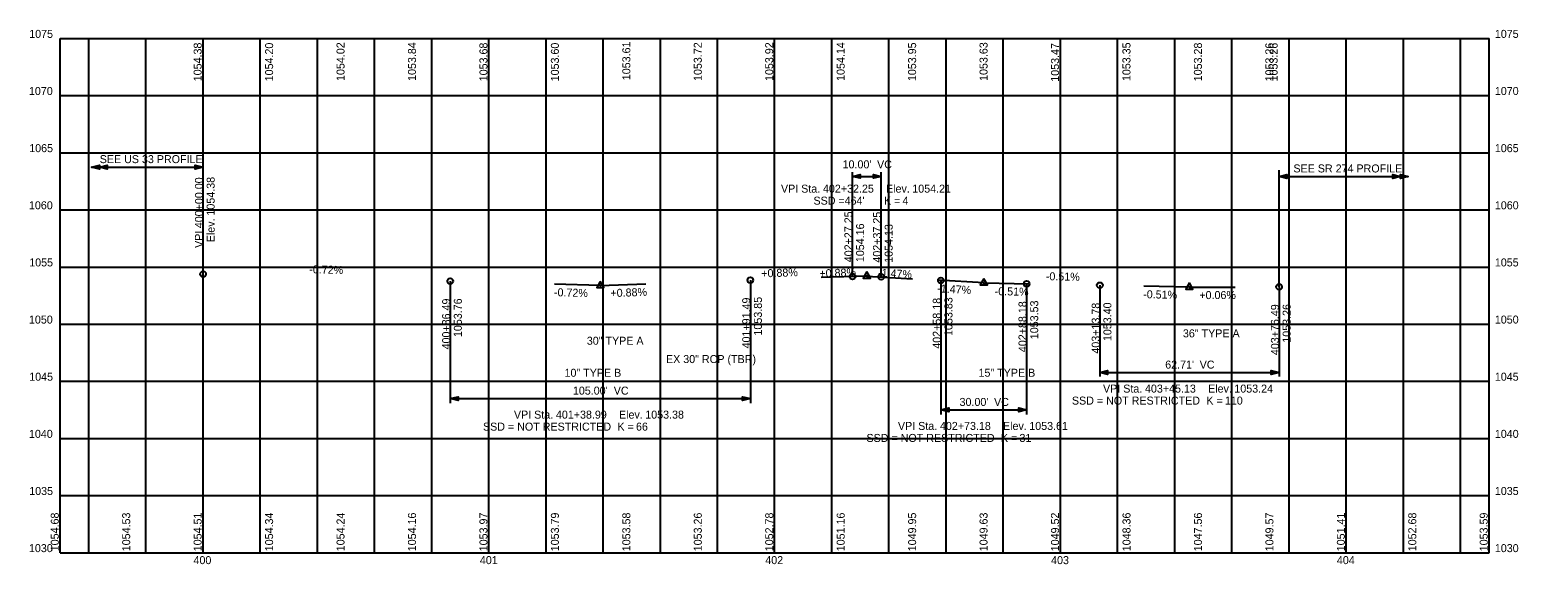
# Model space of a CAD drawing. Extents: x 89 to 610, y 1026 to 1213.
import ezdxf

# ---------------------------------------------------------------- set-up
doc = ezdxf.new("R2010")
doc.units = 0
for name, color, linetype in [('PF_P_Sta_Elev_Text', 7, 'Continuous'), ('PF_P_Text', 7, 'Continuous'), ('PF_P_Text_Curve', 7, 'Continuous'), ('PF_P_Text_Grade', 7, 'Continuous'), ('PF_P_Text_Points', 7, 'Continuous'), ('PF_P_Text_Strip_Grades_20', 7, 'Continuous'), ('PF_X_Text_Strip_Grade', 7, 'Continuous'), ('SH_Major_Grid_Line', 7, 'Continuous')]:
    doc.layers.add(name, color=color, linetype=linetype)

msp = doc.modelspace()

# ---------------------------------------------------------------- linework, layer by layer
at = {"layer": 'PF_P_Text'}
for points in [[(382.25, 1128.28), (381, 1126.11), (383.5, 1126.11)], [(423.18, 1125.87), (421.93, 1123.71), (424.43, 1123.71)], [(288.99, 1124.98), (287.74, 1122.81), (290.24, 1122.81)], [(495.13, 1124.41), (493.88, 1122.24), (496.38, 1122.24)]]:
    msp.add_lwpolyline(points, close=True, dxfattribs=at)
at = {"layer": 'PF_P_Text_Curve'}
for p, q in [((111.01, 1165.06), (111.01, 1164.86)), ((111.01, 1164.96), (150, 1164.96)), ((113.73, 1165.06), (113.73, 1164.86)), ((150, 1164.86), (150, 1165.06)), ((377.25, 1158.06), (377.25, 1163.23)), ((377.25, 1161.83), (377.25, 1161.63)), ((377.25, 1161.73), (387.25, 1161.73)), ((387.25, 1158.06), (387.25, 1163.23)), ((387.25, 1161.63), (387.25, 1161.83)), ((526.49, 1161.8), (526.49, 1161.6)), ((526.49, 1161.7), (571.68, 1161.7)), ((568.97, 1161.6), (568.97, 1161.8)), ((571.68, 1161.6), (571.68, 1161.8)), ((377.25, 1126.66), (377.25, 1158.06)), ((387.25, 1126.54), (387.25, 1158.06)), ((236.49, 1125.04), (236.49, 1093.64)), ((341.49, 1125.39), (341.49, 1093.64)), ((408.18, 1125.31), (408.18, 1092.72)), ((438.18, 1124.12), (438.18, 1092.72)), ((463.78, 1123.6), (463.78, 1091.64)), ((526.49, 1123.04), (526.49, 1091.64)), ((236.49, 1093.64), (236.49, 1082.35)), ((341.49, 1093.64), (341.49, 1082.35)), ((408.18, 1092.72), (408.18, 1078.39)), ((438.18, 1092.72), (438.18, 1078.39)), ((463.78, 1093.14), (463.78, 1092.94)), ((463.78, 1093.04), (526.49, 1093.04)), ((526.49, 1092.94), (526.49, 1093.14)), ((236.49, 1084.03), (236.49, 1083.83)), ((236.49, 1083.93), (341.49, 1083.93)), ((341.49, 1083.83), (341.49, 1084.03)), ((408.18, 1080.07), (408.18, 1079.87)), ((408.18, 1079.97), (438.18, 1079.97)), ((438.18, 1079.87), (438.18, 1080.07))]:
    msp.add_line(p, q, dxfattribs=at)
for points in [[(111.01, 1164.96), (113.73, 1165.64), (113.73, 1164.28)], [(113.73, 1164.96), (116.45, 1165.64), (116.45, 1164.28)], [(150, 1164.96), (147.28, 1164.28), (147.28, 1165.64)], [(377.25, 1161.73), (379.97, 1162.41), (379.97, 1161.05)], [(387.25, 1161.73), (384.53, 1161.05), (384.53, 1162.41)], [(526.49, 1161.7), (529.2, 1162.37), (529.2, 1161.02)], [(568.97, 1161.7), (566.25, 1161.02), (566.25, 1162.37)], [(571.68, 1161.7), (568.97, 1161.02), (568.97, 1162.37)], [(463.78, 1093.04), (466.49, 1093.72), (466.49, 1092.36)], [(526.49, 1093.04), (523.77, 1092.36), (523.77, 1093.72)], [(236.49, 1083.93), (239.21, 1084.61), (239.21, 1083.25)], [(341.49, 1083.93), (338.78, 1083.25), (338.78, 1084.61)], [(408.18, 1079.97), (410.89, 1080.65), (410.89, 1079.29)], [(438.18, 1079.97), (435.46, 1079.29), (435.46, 1080.65)]]:
    msp.add_lwpolyline(points, close=True, dxfattribs=at)
for centre in [(236.49, 1125.04), (341.49, 1125.39), (377.25, 1126.66), (387.25, 1126.54), (408.18, 1125.31), (438.18, 1124.12), (463.78, 1123.6), (526.49, 1123.04)]:
    msp.add_circle(centre, 1, dxfattribs=at)
at = {"layer": 'PF_P_Text_Grade'}
for p, q in [((382.25, 1126.83), (366.26, 1126.27)), ((382.25, 1126.83), (382.25, 1126.83)), ((382.25, 1126.83), (398.22, 1125.89)), ((423.18, 1124.43), (407.2, 1125.37)), ((288.99, 1123.53), (273, 1123.99)), ((288.99, 1123.53), (304.98, 1124.1)), ((288.99, 1123.53), (288.99, 1123.53)), ((423.18, 1124.43), (423.18, 1124.43)), ((423.18, 1124.43), (439.17, 1124.1)), ((495.13, 1122.96), (479.14, 1123.29)), ((495.13, 1122.96), (511.13, 1123)), ((495.13, 1122.96), (495.13, 1122.96))]:
    msp.add_line(p, q, dxfattribs=at)
for centre in [(382.25, 1126.83), (382.25, 1126.83), (288.99, 1123.53), (288.99, 1123.53), (423.18, 1124.43), (423.18, 1124.43), (495.13, 1122.96), (495.13, 1122.96)]:
    msp.add_circle(centre, 0.1, dxfattribs=at)
at = {"layer": 'PF_P_Text_Points'}
for p, q in [((150, 1162.52), (150, 1164.96)), ((150, 1127.52), (150, 1162.52)), ((526.49, 1158.4), (526.49, 1163.92)), ((526.49, 1123.04), (526.49, 1158.4))]:
    msp.add_line(p, q, dxfattribs=at)
msp.add_circle((150, 1127.52), 1, dxfattribs=at)
at = {"layer": 'SH_Major_Grid_Line'}
for p, q in [((100, 1210), (600, 1210)), ((100, 1030), (100, 1210)), ((110, 1030), (110, 1210)), ((130, 1030), (130, 1210)), ((150, 1030), (150, 1210)), ((170, 1030), (170, 1210)), ((190, 1030), (190, 1210)), ((210, 1030), (210, 1210)), ((230, 1030), (230, 1210)), ((250, 1030), (250, 1210)), ((270, 1030), (270, 1210)), ((290, 1030), (290, 1210)), ((310, 1030), (310, 1210)), ((330, 1030), (330, 1210)), ((350, 1030), (350, 1210)), ((370, 1030), (370, 1210)), ((390, 1030), (390, 1210)), ((410, 1030), (410, 1210)), ((430, 1030), (430, 1210)), ((450, 1030), (450, 1210)), ((470, 1030), (470, 1210)), ((490, 1030), (490, 1210)), ((510, 1030), (510, 1210)), ((530, 1030), (530, 1210)), ((550, 1030), (550, 1210)), ((570, 1030), (570, 1210)), ((590, 1030), (590, 1210)), ((600, 1030), (600, 1210)), ((100, 1190), (600, 1190)), ((100, 1170), (600, 1170)), ((100, 1150), (600, 1150)), ((100, 1130), (600, 1130)), ((100, 1110), (600, 1110)), ((100, 1090), (600, 1090)), ((100, 1070), (600, 1070)), ((100, 1050), (600, 1050)), ((100, 1030), (600, 1030))]:
    msp.add_line(p, q, dxfattribs=at)

# ---------------------------------------------------------------- texts
at = {"layer": 'PF_P_Sta_Elev_Text'}
for s, p in [('1075', (89.16, 1210.2)), ('1075', (602, 1210.2)), ('1070', (89.07, 1190.2)), ('1070', (602, 1190.2)), ('1065', (89.16, 1170.2)), ('1065', (602, 1170.2)), ('1060', (89.07, 1150.2)), ('1060', (602, 1150.2)), ('1055', (89.16, 1130.2)), ('1055', (602, 1130.2)), ('1050', (89.07, 1110.2)), ('1050', (602, 1110.2)), ('1045', (89.16, 1090.2)), ('1045', (602, 1090.2)), ('1040', (89.07, 1070.2)), ('1040', (602, 1070.2)), ('1035', (89.16, 1050.2)), ('1035', (602, 1050.2)), ('1030', (89.07, 1030.2)), ('1030', (602, 1030.2)), ('400', (146.65, 1026)), ('401', (246.85, 1026)), ('402', (346.72, 1026)), ('403', (446.73, 1026)), ('404', (546.73, 1026))]:
    msp.add_text(s, height=2.8, dxfattribs=at).set_placement(p)
at = {"layer": 'PF_P_Text_Curve'}
for s, p in [('SEE US 33 PROFILE', (113.84, 1166.36)), ("10.00'", (373.77, 1164.53)), (' VC', (384.8, 1164.53)), ('SEE SR 274 PROFILE', (531.52, 1163.1)), ('VPI Sta. ', (352.21, 1156.03)), ('402+32.25', (366.9, 1156.03)), ('   Elev. ', (385.85, 1156.03)), ('1054.21', (398.16, 1156.03)), ('SSD = ', (363.58, 1151.83)), ("464'", (374.47, 1151.83)), ('K = ', (388.25, 1151.83)), ('4', (394.73, 1151.83)), ('30" TYPE A', (284.27, 1102.79)), ('36" TYPE A', (492.85, 1105.38)), ('EX 30" RCP (TBR)', (311.98, 1096.38)), ('10" TYPE B', (276.47, 1091.58)), ('15" TYPE B', (421.33, 1091.59)), ("62.71'", (486.66, 1094.44)), (' VC', (497.68, 1094.44)), ('VPI Sta. ', (464.9, 1086.04)), ('403+45.13', (479.58, 1086.04)), ('   Elev. ', (498.54, 1086.04)), ('1053.24', (510.85, 1086.04)), ("105.00'", (279.4, 1085.33)), (' VC', (292.66, 1085.33)), ("30.00'", (414.7, 1081.37)), (' VC', (425.73, 1081.37)), ('SSD = NOT RESTRICTED', (454.01, 1081.84)), ('K = ', (501.05, 1081.84)), ('110', (507.54, 1081.84)), ('VPI Sta. ', (258.77, 1076.93)), ('401+38.99', (273.46, 1076.93)), ('   Elev. ', (292.41, 1076.93)), ('1053.38', (304.72, 1076.93)), ('SSD = NOT RESTRICTED', (247.94, 1072.73)), ('K = ', (294.99, 1072.73)), ('66', (301.48, 1072.73)), ('VPI Sta. ', (393.14, 1072.97)), ('402+73.18', (407.83, 1072.97)), ('   Elev. ', (426.78, 1072.97)), ('1053.61', (439.09, 1072.97)), ('SSD = NOT RESTRICTED', (382.13, 1068.77)), ('K = ', (429.18, 1068.77)), ('31', (435.66, 1068.77))]:
    msp.add_text(s, height=2.8, dxfattribs=at).set_placement(p)
at = {"layer": 'PF_P_Text_Grade'}
for s, rotation, p in [('-0.72%', 358.3552, (187.13, 1127.86)), ('+0.88%', 2.0271, (345.36, 1126.34)), ('+0.88%', 2.0271, (365.71, 1126.33)), ('-1.47%', 356.639, (386.12, 1126.68)), ('-0.51%', 358.8325, (444.86, 1125.39)), ('-0.72%', 358.3552, (272.75, 1119.8)), ('+0.88%', 2.0271, (292.59, 1119.46)), ('-1.47%', 356.639, (406.83, 1121.18)), ('-0.51%', 358.8325, (426.97, 1120.15)), ('-0.51%', 358.8325, (478.93, 1119.09)), ('+0.06%', 0.1414, (498.6, 1118.77))]:
    msp.add_text(s, height=2.8, rotation=rotation, dxfattribs=at).set_placement(p)
at = {"layer": 'PF_P_Text_Points'}
for s, p in [('400+00.00', (149.96, 1143.58)), ('1054.38', (154.05, 1148)), ('Elev. ', (154.05, 1138.68)), ('402+27.25', (377.21, 1131.66)), ('402+37.25', (387.21, 1131.54)), ('VPI ', (149.96, 1136.69)), ('1054.16', (381.3, 1131.7)), ('1054.13', (391.3, 1131.47)), ('400+86.49', (236.45, 1101.15)), ('1053.76', (240.54, 1105.47)), ('401+91.49', (341.45, 1101.5)), ('1053.85', (345.54, 1106.01)), ('402+58.18', (408.13, 1101.39)), ('1053.83', (412.22, 1105.87)), ('402+88.18', (438.13, 1100.2)), ('1053.53', (442.23, 1104.73)), ('403+13.78', (463.74, 1099.68)), ('1053.40', (467.83, 1104.06)), ('403+76.49', (526.45, 1099.15)), ('1053.26', (530.54, 1103.51))]:
    msp.add_text(s, height=2.8, rotation=90, dxfattribs=at).set_placement(p)
at = {"layer": 'PF_P_Text_Strip_Grades_20'}
for s, p in [('1054.38', (149.5, 1195.01)), ('1054.38', (149.5, 1195.01)), ('1054.20', (174.5, 1194.99)), ('1054.02', (199.5, 1195.12)), ('1053.84', (224.5, 1195.14)), ('1053.68', (249.5, 1195.01)), ('1053.60', (274.5, 1194.99)), ('1053.61', (299.5, 1195.38)), ('1053.72', (324.5, 1195.12)), ('1053.92', (349.5, 1195.12)), ('1054.14', (374.5, 1195.14)), ('1053.95', (399.5, 1195.07)), ('1053.63', (424.5, 1195.14)), ('1053.35', (474.5, 1195.07)), ('1053.28', (499.5, 1195.01)), ('1053.26', (524.5, 1194.96)), ('1053.26', (525.99, 1194.96)), ('1053.47', (449.5, 1194.85))]:
    msp.add_text(s, height=2.8, rotation=90, dxfattribs=at).set_placement(p)
at = {"layer": 'PF_X_Text_Strip_Grade'}
for s, p in [('1054.68', (99.5, 1030.5)), ('1054.53', (124.5, 1030.5)), ('1054.51', (149.5, 1030.5)), ('1054.34', (174.5, 1030.5)), ('1054.24', (199.5, 1030.5)), ('1054.16', (224.5, 1030.5)), ('1053.97', (249.5, 1030.5)), ('1053.79', (274.5, 1030.5)), ('1053.58', (299.5, 1030.5)), ('1053.26', (324.5, 1030.5)), ('1052.78', (349.5, 1030.5)), ('1051.16', (374.5, 1030.5)), ('1049.95', (399.51, 1030.5)), ('1049.63', (424.5, 1030.5)), ('1049.52', (449.5, 1030.5)), ('1048.36', (474.52, 1030.5)), ('1047.56', (499.52, 1030.5)), ('1049.57', (524.52, 1030.5)), ('1051.41', (549.52, 1030.5)), ('1052.68', (574.51, 1030.5)), ('1053.59', (599.51, 1030.5))]:
    msp.add_text(s, height=2.8, rotation=90, dxfattribs=at).set_placement(p)

doc.saveas('drawing.dxf')
